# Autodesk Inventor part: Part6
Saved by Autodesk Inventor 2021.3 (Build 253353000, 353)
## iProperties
Created: 2022-07
Part Number: Part6
Material: Generic
Document SubType Name: Modeling
Designer: Administrator
Density: 1 g/cm^3
Appearance: Default
Author: Administrator
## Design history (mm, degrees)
feature "Body1"
body "Solid1"
